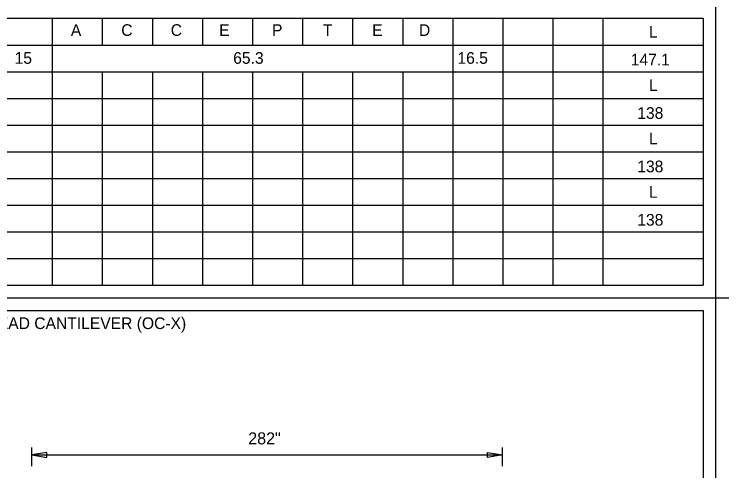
# Model space of a CAD drawing. Extents: x 10268259 to 10268554, y 2141099 to 2141249.
# Drawn here: x 10268352.7 to 10268395.1, y 2141145.91 to 2141173.28 of the extents above; entities that cross this region are included whole.
import ezdxf

# ---------------------------------------------------------------- set-up
doc = ezdxf.new("R2010")
doc.units = 0
for name, color, linetype in [('60', 7, 'Continuous'), ('61', 7, 'Continuous'), ('62', 7, 'Continuous'), ('GSDims', 7, 'Continuous'), ('SheetBorder_dp', 7, 'Continuous')]:
    doc.layers.add(name, color=color, linetype=linetype)

msp = doc.modelspace()

# ---------------------------------------------------------------- linework, layer by layer
at = {"layer": '60'}
for p, q in [((10268318.48, 2141173.028), (10268393.98, 2141173.028)), ((10268354.98, 2141173.028), (10268354.98, 2141171.428)), ((10268357.98, 2141173.028), (10268357.98, 2141171.428)), ((10268360.98, 2141173.028), (10268360.98, 2141171.428)), ((10268363.98, 2141173.028), (10268363.98, 2141171.428)), ((10268366.98, 2141173.028), (10268366.98, 2141171.428)), ((10268369.98, 2141173.028), (10268369.98, 2141171.428)), ((10268372.98, 2141173.028), (10268372.98, 2141171.428)), ((10268375.98, 2141173.028), (10268375.98, 2141171.428)), ((10268378.98, 2141173.028), (10268378.98, 2141171.428)), ((10268381.98, 2141173.028), (10268381.98, 2141171.428)), ((10268384.98, 2141173.028), (10268384.98, 2141171.428)), ((10268387.98, 2141173.028), (10268387.98, 2141171.428)), ((10268393.98, 2141173.028), (10268393.98, 2141157.028)), ((10268354.98, 2141171.428), (10268354.98, 2141166.628)), ((10268378.98, 2141171.428), (10268378.98, 2141165.028)), ((10268381.98, 2141171.428), (10268381.98, 2141165.028)), ((10268384.98, 2141171.428), (10268384.98, 2141165.028)), ((10268387.98, 2141171.428), (10268387.98, 2141157.028)), ((10268318.48, 2141169.828), (10268393.98, 2141169.828)), ((10268357.98, 2141169.828), (10268357.98, 2141166.628)), ((10268360.98, 2141169.828), (10268360.98, 2141166.628)), ((10268363.98, 2141169.828), (10268363.98, 2141166.628)), ((10268366.98, 2141169.828), (10268366.98, 2141165.028)), ((10268369.98, 2141169.828), (10268369.98, 2141165.028)), ((10268372.98, 2141169.828), (10268372.98, 2141157.028)), ((10268375.98, 2141169.828), (10268375.98, 2141157.028)), ((10268318.48, 2141166.628), (10268393.98, 2141166.628)), ((10268354.98, 2141166.628), (10268354.98, 2141157.028)), ((10268357.98, 2141166.628), (10268357.98, 2141157.028)), ((10268360.98, 2141166.628), (10268360.98, 2141157.028)), ((10268363.98, 2141166.628), (10268363.98, 2141157.028)), ((10268366.98, 2141165.028), (10268366.98, 2141157.028)), ((10268369.98, 2141165.028), (10268369.98, 2141157.028)), ((10268378.98, 2141165.028), (10268378.98, 2141157.028)), ((10268381.98, 2141165.028), (10268381.98, 2141157.028)), ((10268384.98, 2141165.028), (10268384.98, 2141157.028)), ((10268318.48, 2141163.428), (10268393.98, 2141163.428)), ((10268318.48, 2141160.228), (10268393.98, 2141160.228)), ((10268318.48, 2141157.028), (10268393.98, 2141157.028)), ((10268341.73, 2141155.528), (10268393.98, 2141155.528)), ((10268393.98, 2141155.528), (10268393.98, 2141125.528))]:
    msp.add_line(p, q, dxfattribs=at)
at = {"layer": '61'}
for p, q in [((10268318.48, 2141171.428), (10268393.98, 2141171.428)), ((10268318.48, 2141168.228), (10268393.98, 2141168.228)), ((10268318.48, 2141165.028), (10268393.98, 2141165.028)), ((10268318.48, 2141161.828), (10268393.98, 2141161.828)), ((10268318.48, 2141158.628), (10268393.98, 2141158.628))]:
    msp.add_line(p, q, dxfattribs=at)
at = {"layer": 'GSDims'}
for p, q in [((10268353.754, 2141146.193), (10268353.754, 2141147.318)), ((10268381.954, 2141146.193), (10268381.954, 2141147.318)), ((10268353.754, 2141146.868), (10268381.954, 2141146.868))]:
    msp.add_line(p, q, dxfattribs=at)
for points in [[(10268353.754, 2141146.868), (10268354.654, 2141146.718), (10268354.654, 2141147.018)], [(10268381.954, 2141146.868), (10268381.054, 2141146.718), (10268381.054, 2141147.018)]]:
    msp.add_lwpolyline(points, close=True, dxfattribs=at)
at = {"layer": 'SheetBorder_dp'}
for p, q in [((10268394.73, 2141204.278), (10268394.73, 2141108.278)), ((10268317.73, 2141156.278), (10268471.73, 2141156.278))]:
    msp.add_line(p, q, dxfattribs=at)

# ---------------------------------------------------------------- texts
at = {"layer": '62'}
for s, p in [('A', (10268356.097, 2141171.973)), ('C', (10268359.116, 2141171.973)), ('C', (10268362.082, 2141171.973)), ('E', (10268364.979, 2141171.973)), ('P', (10268368.152, 2141171.973)), ('T', (10268371.201, 2141171.973)), ('E', (10268374.149, 2141171.973)), ('D', (10268376.954, 2141171.973)), ('L', (10268390.733, 2141171.873)), ('15', (10268352.726, 2141170.303)), ('65.3', (10268365.825, 2141170.303)), ('16.5', (10268379.262, 2141170.303)), ('147.1', (10268389.646, 2141170.203)), ('L', (10268390.733, 2141168.673)), ('138', (10268390.037, 2141167.003)), ('L', (10268390.733, 2141165.473)), ('138', (10268390.037, 2141163.803)), ('L', (10268390.733, 2141162.273)), ('138', (10268390.037, 2141160.603)), ('MOUNTING:  OVERHEAD CANTILEVER (OC-X)', (10268342.516, 2141154.407))]:
    msp.add_text(s, height=0.7, dxfattribs=at).set_placement(p)
at = {"layer": 'GSDims'}
msp.add_text('282"', height=0.72, dxfattribs=at).set_placement((10268366.724, 2141147.498))

doc.saveas('drawing.dxf')
